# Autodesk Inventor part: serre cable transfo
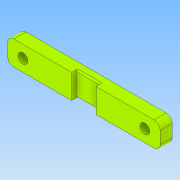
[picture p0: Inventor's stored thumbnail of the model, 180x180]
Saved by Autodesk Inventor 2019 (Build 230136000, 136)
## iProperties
Created: 2024-09
Part Number: serre cable transfo
Material: Générique
Document SubType Name: Modeling
Designer: admin
Density: 1 g/cm^3
Appearance: Par défaut
Author: admin
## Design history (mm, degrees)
sketch "Esquisse1"
  geometry: L1 (-25, 4)-(25, 4); L2 (25, 4)-(25, -4); L3 (25, -4)-(-25, -4); L4 (-25, -4)-(-25, 4); C1 r 1.6 at (-20, 0); C2 r 1.6 at (20, 0); 1 further point
  constraints: 8 end point, 2 centre point, 2 parallel, 1 horizontal, 1 perpendicular
  dimensions: "d0" = 8 distance of L1.end L2.end; "d1" = 4 distance from line of L1 point (0, 0) (= 0.5 x d0); "d2" = 50 distance of L1.start L1.end; "d3" = 25 distance from line of point (0, 0) L4 (= 0.5 x d2); "d4" = 3.2 diameter of C1; "d5" = 3.2 diameter of C2; "d6" = 20 distance of point (0, 0) C1.centre; "d7" = 20 distance of point (0, 0) C2.centre
extrude "Extrusion1" new body sketch "Esquisse1" distance "d8" = 4; taper "d9" = 0 deg
sketch "Esquisse2"
  geometry: L1 (25, 4)-(-25, 4) reference; L2 (-25, 4)-(-25, -4) reference; L3 (-25, -4)-(25, -4) reference; L4 (25, -4)-(25, 4) reference; L5 (-25, -4)-(25, -4) reference; L6 (-4, 4)-(4, 4); L7 (4, 4)-(4, -4); L8 (4, -4)-(-4, -4); L9 (-4, -4)-(-4, 4); C1 r 1.6 at (20, 0) reference; C2 r 1.6 at (-20, 0) reference; 1 further point
  constraints: 8 end point, 2 parallel, 2 point on line, 1 horizontal, 1 perpendicular
  dimensions: "d10" = 8 distance between parallel lines of L7 L9; "d11" = 4 distance from line of point (0, 0) L9 (= 0.5 x d10)
extrude "Extrusion2" cut sketch "Esquisse2" distance "d12" = 1.5; taper "d13" = 0 deg
fillet "Congé1" dims "d14" = 2
chamfer "Chanfrein1" distance "d15" = 0.5; stored, may be unused: second distance "d16" = 2, angle "d17" = 45 deg
node "Solide1"
node "Boucle projetée1"
